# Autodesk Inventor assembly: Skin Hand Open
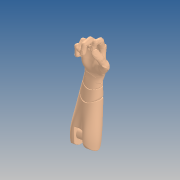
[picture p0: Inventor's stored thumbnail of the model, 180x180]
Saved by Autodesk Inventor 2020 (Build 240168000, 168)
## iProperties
Created: 2019-10
Part Number: Skin Hand Open
Document SubType Name: Assembly
Designer: yello
Author: yello
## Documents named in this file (21)
- C:\Users\yello\Documents\Mechanical Hand\Prototype 2 (Realistic Hand)\Skin Hand Open.iam
- C:\Users\yello\Documents\Mechanical Hand\Prototype 2 (Realistic Hand)\Palm.ipt
- C:\Users\yello\Documents\Mechanical Hand\Prototype 2 (Realistic Hand)\Wrist Rotation.ipt
- C:\Users\yello\Documents\Mechanical Hand\Prototype 2 (Realistic Hand)\Arm to Wrist Connection.ipt
- C:\Users\yello\Documents\Mechanical Hand\Prototype 2 (Realistic Hand)\Arm.ipt
- C:\Users\yello\Documents\Mechanical Hand\Prototype 2 (Realistic Hand)\Segment Thumb Finger Bottom.ipt
- C:\Users\yello\Documents\Mechanical Hand\Prototype 2 (Realistic Hand)\Segment Thumb Finger Middle.ipt
- C:\Users\yello\Documents\Mechanical Hand\Prototype 2 (Realistic Hand)\Segment Thumb Finger Top.ipt
- C:\Users\yello\Documents\Mechanical Hand\Prototype 2 (Realistic Hand)\Segment Index Finger Middle.ipt
- C:\Users\yello\Documents\Mechanical Hand\Prototype 2 (Realistic Hand)\Segment Index Finger Top.ipt
- C:\Users\yello\Documents\Mechanical Hand\Prototype 2 (Realistic Hand)\Segment Middle Finger Middle.ipt
- C:\Users\yello\Documents\Mechanical Hand\Prototype 2 (Realistic Hand)\Segment Middle Finger Top.ipt
- C:\Users\yello\Documents\Mechanical Hand\Prototype 2 (Realistic Hand)\Segment Ring Finger Middle.ipt
- C:\Users\yello\Documents\Mechanical Hand\Prototype 2 (Realistic Hand)\Segment Ring Finger Top.ipt
- C:\Users\yello\Documents\Mechanical Hand\Prototype 2 (Realistic Hand)\Segment Pinkie Finger Middle.ipt
- C:\Users\yello\Documents\Mechanical Hand\Prototype 2 (Realistic Hand)\Segment Pinkie Finger Top.ipt
- C:\Users\yello\Documents\Mechanical Hand\Prototype 2 (Realistic Hand)\Segment Index Finger Bottom Ball.iam
- C:\Users\yello\Documents\Mechanical Hand\Prototype 2 (Realistic Hand)\Segment Middle Finger Bottom Ball.iam
- C:\Users\yello\Documents\Mechanical Hand\Prototype 2 (Realistic Hand)\Segment Ring Finger Bottom Ball.iam
- C:\Users\yello\Documents\Mechanical Hand\Prototype 2 (Realistic Hand)\Segment Pinkie Finger Bottom Ball.iam
- C:\Users\yello\Documents\Mechanical Hand\Prototype 2 (Realistic Hand)\Bearings.iam
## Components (23 placed, 20 different names)
1. Palm:1 — Rotational:1, Rotational:2, Rotational:17, Rotational:18, Rotational:19, Rotational:20
2. Wrist Rotation:1 — Rotational:1, Mate:1, Mate:2, Mate:4
3. Arm to Wrist Connection:1 — Mate:1, Mate:2, Mate:3
4. Arm:1 — Mate:3, Mate:4
5. Segment Thumb Finger Bottom:1 — Rotational:2, Rotational:3
6. Segment Thumb Finger Middle:1 — Rotational:3, Rotational:4
7. Segment Thumb Finger Top:1 — Rotational:4
8. Segment Index Finger Middle:1 — Rotational:24, Rotational:25, Mate:5, Flush:1
9. Segment Index Finger Top:1 — Rotational:25
10. Segment Middle Finger Middle:1 — Rotational:10, Rotational:23, Mate:6, Flush:2
11. Segment Middle Finger Top:1 — Rotational:10
12. Segment Ring Finger Middle:1 — Rotational:13, Rotational:22, Mate:7, Flush:3
13. Segment Ring Finger Top:1 — Rotational:13
14. Segment Pinkie Finger Middle:1 — Rotational:16, Rotational:21, Mate:8, Flush:4
15. Segment Pinkie Finger Top:1 — Rotational:16
16. Segment Index Finger Bottom Ball:1 [sub-assembly] — Rotational:17, Rotational:24
17. Segment Middle Finger Bottom Ball:1 [sub-assembly] — Rotational:18, Rotational:23
18. Segment Ring Finger Bottom Ball:1 [sub-assembly] — Rotational:19, Rotational:22
19. Segment Pinkie Finger Bottom Ball:1 [sub-assembly] — Rotational:20, Rotational:21
20. Bearings:1 [sub-assembly] — Mate:5, Flush:1
21. Bearings:2 [sub-assembly] — Mate:6, Flush:2
22. Bearings:3 [sub-assembly] — Mate:7, Flush:3
23. Bearings:4 [sub-assembly] — Mate:8, Flush:4
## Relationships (28: RevoluteJoint 16, Mate 8, Flush 4)
- Rotational:1 [RevoluteJoint]: Palm:1 ↔ Wrist Rotation:1
- Mate:1: Wrist Rotation:1 ↔ Arm to Wrist Connection:1
- Mate:2: Wrist Rotation:1 ↔ Arm to Wrist Connection:1
- Mate:3: Arm to Wrist Connection:1 ↔ Arm:1
- Mate:4: Wrist Rotation:1 ↔ Arm:1
- Rotational:2 [RevoluteJoint]: Palm:1 ↔ Segment Thumb Finger Bottom:1
- Rotational:3 [RevoluteJoint]: Segment Thumb Finger Bottom:1 ↔ Segment Thumb Finger Middle:1
- Rotational:4 [RevoluteJoint]: Segment Thumb Finger Middle:1 ↔ Segment Thumb Finger Top:1
- Rotational:10 [RevoluteJoint]: Segment Middle Finger Middle:1 ↔ Segment Middle Finger Top:1
- Rotational:13 [RevoluteJoint]: Segment Ring Finger Middle:1 ↔ Segment Ring Finger Top:1
- Rotational:16 [RevoluteJoint]: Segment Pinkie Finger Middle:1 ↔ Segment Pinkie Finger Top:1
- Rotational:17 [RevoluteJoint]: Palm:1 ↔ Segment Index Finger Bottom Ball:1
- Rotational:18 [RevoluteJoint]: Palm:1 ↔ Segment Middle Finger Bottom Ball:1
- Rotational:19 [RevoluteJoint]: Palm:1 ↔ Segment Ring Finger Bottom Ball:1
- Rotational:20 [RevoluteJoint]: Palm:1 ↔ Segment Pinkie Finger Bottom Ball:1
- Rotational:21 [RevoluteJoint]: Segment Pinkie Finger Middle:1 ↔ Segment Pinkie Finger Bottom Ball:1
- Rotational:22 [RevoluteJoint]: Segment Ring Finger Middle:1 ↔ Segment Ring Finger Bottom Ball:1
- Rotational:23 [RevoluteJoint]: Segment Middle Finger Middle:1 ↔ Segment Middle Finger Bottom Ball:1
- Rotational:24 [RevoluteJoint]: Segment Index Finger Middle:1 ↔ Segment Index Finger Bottom Ball:1
- Rotational:25 [RevoluteJoint]: Segment Index Finger Middle:1 ↔ Segment Index Finger Top:1
- Mate:5: Segment Index Finger Middle:1 ↔ Bearings:1
- Flush:1: Segment Index Finger Middle:1 ↔ Bearings:1
- Mate:6: Segment Middle Finger Middle:1 ↔ Bearings:2
- Flush:2: Segment Middle Finger Middle:1 ↔ Bearings:2
- Mate:7: Segment Ring Finger Middle:1 ↔ Bearings:3
- Flush:3: Segment Ring Finger Middle:1 ↔ Bearings:3
- Mate:8: Segment Pinkie Finger Middle:1 ↔ Bearings:4
- Flush:4: Segment Pinkie Finger Middle:1 ↔ Bearings:4
